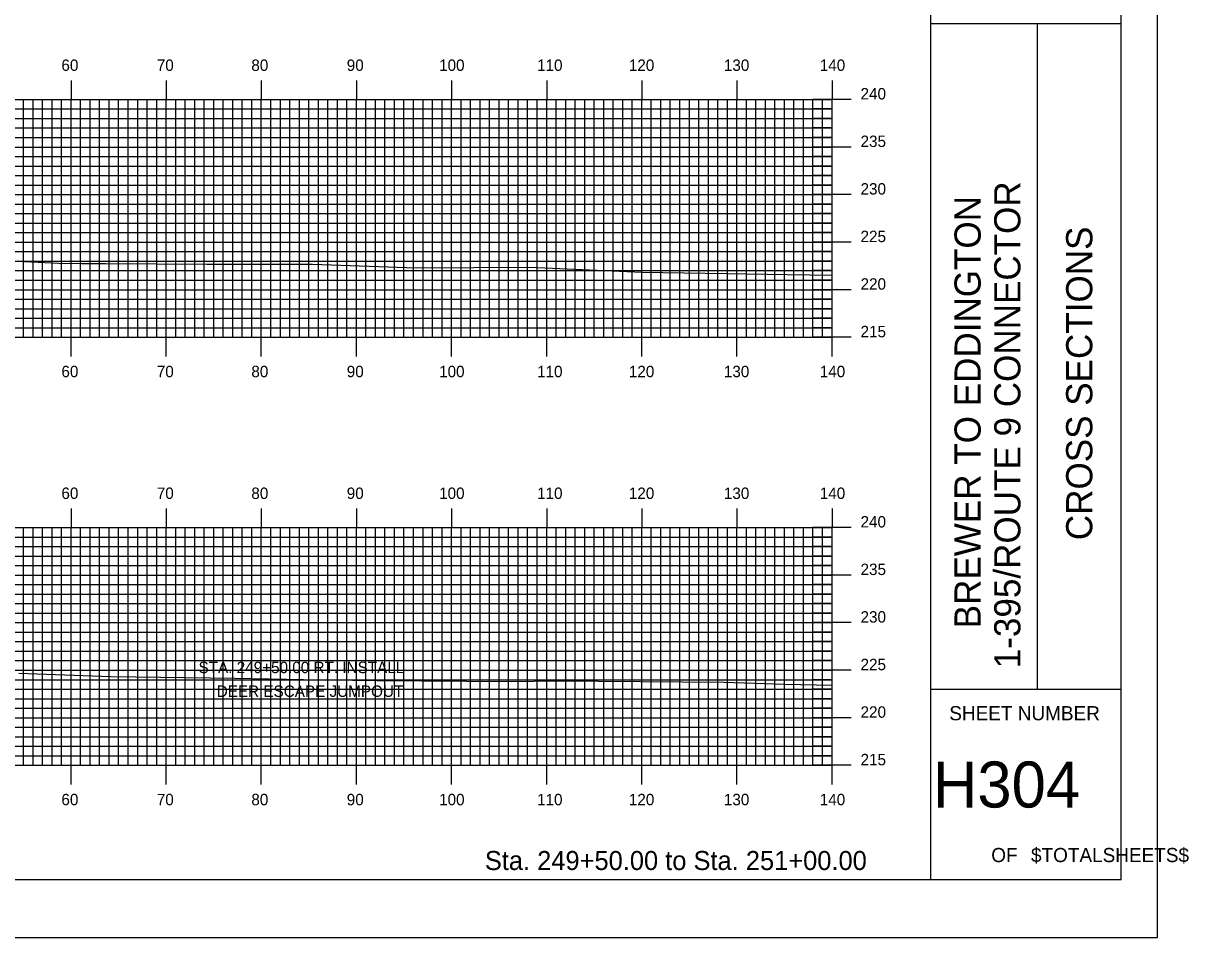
# Model space of a CAD drawing. Extents: x 1803897 to 1804240, y 442591 to 442811.
# Drawn here: x 1804117.6 to 1804240.2, y 442590.5 to 442686.7 of the extents above; entities that cross this region are included whole.
import ezdxf

# ---------------------------------------------------------------- set-up
doc = ezdxf.new("R2010")
doc.units = 0
for name, color, linetype in [('BORDER', 7, 'Continuous'), ('D_Text_Standard', 7, 'Continuous'), ('H_V ANNOTATION', 7, 'Continuous'), ('MAJOR', 7, 'Continuous'), ('MINOR', 7, 'Continuous'), ('PLOT BOUNDARY', 7, 'Continuous'), ('S_Roadway_Centerline', 7, 'Continuous')]:
    doc.layers.add(name, color=color, linetype=linetype)

msp = doc.modelspace()

# ---------------------------------------------------------------- linework, layer by layer
at = {"layer": 'BORDER'}
for p, q in [((1804213.05, 442596.67), (1804213.05, 442806.67)), ((1804213.05, 442686.67), (1804233.05, 442686.67)), ((1804224.24, 442616.67), (1804224.24, 442686.67)), ((1804213.05, 442616.67), (1804233.05, 442616.67))]:
    msp.add_line(p, q, dxfattribs=at)
msp.add_lwpolyline([(1803913.05, 442596.67), (1804233.05, 442596.67), (1804233.05, 442806.67), (1803913.05, 442806.67)], close=True, dxfattribs=at)
at = {"layer": 'MAJOR'}
for p, q in [((1804122.65, 442680.67), (1804122.65, 442678.67)), ((1804132.65, 442680.67), (1804132.65, 442678.67)), ((1804142.65, 442680.67), (1804142.65, 442678.67)), ((1804152.65, 442680.67), (1804152.65, 442678.67)), ((1804162.65, 442680.67), (1804162.65, 442678.67)), ((1804172.65, 442680.67), (1804172.65, 442678.67)), ((1804182.65, 442680.67), (1804182.65, 442678.67)), ((1804192.65, 442680.67), (1804192.65, 442678.67)), ((1804202.65, 442680.67), (1804202.65, 442678.67)), ((1803922.65, 442678.67), (1804202.65, 442678.67)), ((1803922.65, 442678.67), (1804202.65, 442678.67)), ((1804122.65, 442653.67), (1804122.65, 442678.67)), ((1804132.65, 442653.67), (1804132.65, 442678.67)), ((1804142.65, 442653.67), (1804142.65, 442678.67)), ((1804152.65, 442653.67), (1804152.65, 442678.67)), ((1804162.65, 442653.67), (1804162.65, 442678.67)), ((1804172.65, 442653.67), (1804172.65, 442678.67)), ((1804182.65, 442653.67), (1804182.65, 442678.67)), ((1804192.65, 442653.67), (1804192.65, 442678.67)), ((1804204.66, 442678.67), (1804200.65, 442678.67)), ((1804202.65, 442653.67), (1804202.65, 442678.67)), ((1804202.65, 442653.67), (1804202.65, 442678.67)), ((1803922.65, 442673.67), (1804202.65, 442673.67)), ((1804204.66, 442673.67), (1804200.65, 442673.67)), ((1803922.65, 442668.67), (1804202.65, 442668.67)), ((1804204.66, 442668.67), (1804200.65, 442668.67)), ((1803922.65, 442663.67), (1804202.65, 442663.67)), ((1804204.66, 442663.67), (1804200.65, 442663.67)), ((1803922.65, 442658.67), (1804202.65, 442658.67)), ((1804204.66, 442658.67), (1804200.65, 442658.67)), ((1803922.65, 442653.67), (1804202.65, 442653.67)), ((1803922.65, 442653.67), (1804202.65, 442653.67)), ((1804122.65, 442651.66), (1804122.65, 442653.67)), ((1804132.65, 442651.66), (1804132.65, 442653.67)), ((1804142.65, 442651.66), (1804142.65, 442653.67)), ((1804152.65, 442651.66), (1804152.65, 442653.67)), ((1804162.65, 442651.66), (1804162.65, 442653.67)), ((1804172.65, 442651.66), (1804172.65, 442653.67)), ((1804182.65, 442651.66), (1804182.65, 442653.67)), ((1804192.65, 442651.66), (1804192.65, 442653.67)), ((1804204.66, 442653.67), (1804200.65, 442653.67)), ((1804202.65, 442651.66), (1804202.65, 442653.67)), ((1804122.65, 442635.67), (1804122.65, 442633.67)), ((1804132.65, 442635.67), (1804132.65, 442633.67)), ((1804142.65, 442635.67), (1804142.65, 442633.67)), ((1804152.65, 442635.67), (1804152.65, 442633.67)), ((1804162.65, 442635.67), (1804162.65, 442633.67)), ((1804172.65, 442635.67), (1804172.65, 442633.67)), ((1804182.65, 442635.67), (1804182.65, 442633.67)), ((1804192.65, 442635.67), (1804192.65, 442633.67)), ((1804202.65, 442635.67), (1804202.65, 442633.67)), ((1803922.65, 442633.67), (1804202.65, 442633.67)), ((1803922.65, 442633.67), (1804202.65, 442633.67)), ((1804122.65, 442608.67), (1804122.65, 442633.67)), ((1804132.65, 442608.67), (1804132.65, 442633.67)), ((1804142.65, 442608.67), (1804142.65, 442633.67)), ((1804152.65, 442608.67), (1804152.65, 442633.67)), ((1804162.65, 442608.67), (1804162.65, 442633.67)), ((1804172.65, 442608.67), (1804172.65, 442633.67)), ((1804182.65, 442608.67), (1804182.65, 442633.67)), ((1804192.65, 442608.67), (1804192.65, 442633.67)), ((1804204.66, 442633.67), (1804200.65, 442633.67)), ((1804202.65, 442608.67), (1804202.65, 442633.67)), ((1804202.65, 442608.67), (1804202.65, 442633.67)), ((1803922.65, 442628.67), (1804202.65, 442628.67)), ((1804204.66, 442628.67), (1804200.65, 442628.67)), ((1803922.65, 442623.67), (1804202.65, 442623.67)), ((1804204.66, 442623.67), (1804200.65, 442623.67)), ((1803922.65, 442618.67), (1804202.65, 442618.67)), ((1804204.66, 442618.67), (1804200.65, 442618.67)), ((1803922.65, 442613.67), (1804202.65, 442613.67)), ((1804204.66, 442613.67), (1804200.65, 442613.67)), ((1803922.65, 442608.67), (1804202.65, 442608.67)), ((1803922.65, 442608.67), (1804202.65, 442608.67)), ((1804122.65, 442606.66), (1804122.65, 442608.67)), ((1804132.65, 442606.66), (1804132.65, 442608.67)), ((1804142.65, 442606.66), (1804142.65, 442608.67)), ((1804152.65, 442606.66), (1804152.65, 442608.67)), ((1804162.65, 442606.66), (1804162.65, 442608.67)), ((1804172.65, 442606.66), (1804172.65, 442608.67)), ((1804182.65, 442606.66), (1804182.65, 442608.67)), ((1804192.65, 442606.66), (1804192.65, 442608.67)), ((1804204.66, 442608.67), (1804200.65, 442608.67)), ((1804202.65, 442606.66), (1804202.65, 442608.67))]:
    msp.add_line(p, q, dxfattribs=at)
at = {"layer": 'MINOR'}
for p, q in [((1804117.65, 442653.67), (1804117.65, 442678.67)), ((1804118.65, 442653.67), (1804118.65, 442678.67)), ((1804119.65, 442653.67), (1804119.65, 442678.67)), ((1804120.65, 442653.67), (1804120.65, 442678.67)), ((1804121.65, 442653.67), (1804121.65, 442678.67)), ((1804123.65, 442653.67), (1804123.65, 442678.67)), ((1804124.65, 442653.67), (1804124.65, 442678.67)), ((1804125.65, 442653.67), (1804125.65, 442678.67)), ((1804126.65, 442653.67), (1804126.65, 442678.67)), ((1804127.65, 442653.67), (1804127.65, 442678.67)), ((1804128.65, 442653.67), (1804128.65, 442678.67)), ((1804129.65, 442653.67), (1804129.65, 442678.67)), ((1804130.65, 442653.67), (1804130.65, 442678.67)), ((1804131.65, 442653.67), (1804131.65, 442678.67)), ((1804133.65, 442653.67), (1804133.65, 442678.67)), ((1804134.65, 442653.67), (1804134.65, 442678.67)), ((1804135.65, 442653.67), (1804135.65, 442678.67)), ((1804136.65, 442653.67), (1804136.65, 442678.67)), ((1804137.65, 442653.67), (1804137.65, 442678.67)), ((1804138.65, 442653.67), (1804138.65, 442678.67)), ((1804139.65, 442653.67), (1804139.65, 442678.67)), ((1804140.65, 442653.67), (1804140.65, 442678.67)), ((1804141.65, 442653.67), (1804141.65, 442678.67)), ((1804143.65, 442653.67), (1804143.65, 442678.67)), ((1804144.65, 442653.67), (1804144.65, 442678.67)), ((1804145.65, 442653.67), (1804145.65, 442678.67)), ((1804146.65, 442653.67), (1804146.65, 442678.67)), ((1804147.65, 442653.67), (1804147.65, 442678.67)), ((1804148.65, 442653.67), (1804148.65, 442678.67)), ((1804149.65, 442653.67), (1804149.65, 442678.67)), ((1804150.65, 442653.67), (1804150.65, 442678.67)), ((1804151.65, 442653.67), (1804151.65, 442678.67)), ((1804153.65, 442653.67), (1804153.65, 442678.67)), ((1804154.65, 442653.67), (1804154.65, 442678.67)), ((1804155.65, 442653.67), (1804155.65, 442678.67)), ((1804156.65, 442653.67), (1804156.65, 442678.67)), ((1804157.65, 442653.67), (1804157.65, 442678.67)), ((1804158.65, 442653.67), (1804158.65, 442678.67)), ((1804159.65, 442653.67), (1804159.65, 442678.67)), ((1804160.65, 442653.67), (1804160.65, 442678.67)), ((1804161.65, 442653.67), (1804161.65, 442678.67)), ((1804163.65, 442653.67), (1804163.65, 442678.67)), ((1804164.65, 442653.67), (1804164.65, 442678.67)), ((1804165.65, 442653.67), (1804165.65, 442678.67)), ((1804166.65, 442653.67), (1804166.65, 442678.67)), ((1804167.65, 442653.67), (1804167.65, 442678.67)), ((1804168.65, 442653.67), (1804168.65, 442678.67)), ((1804169.65, 442653.67), (1804169.65, 442678.67)), ((1804170.65, 442653.67), (1804170.65, 442678.67)), ((1804171.65, 442653.67), (1804171.65, 442678.67)), ((1804173.65, 442653.67), (1804173.65, 442678.67)), ((1804174.65, 442653.67), (1804174.65, 442678.67)), ((1804175.65, 442653.67), (1804175.65, 442678.67)), ((1804176.65, 442653.67), (1804176.65, 442678.67)), ((1804177.65, 442653.67), (1804177.65, 442678.67)), ((1804178.65, 442653.67), (1804178.65, 442678.67)), ((1804179.65, 442653.67), (1804179.65, 442678.67)), ((1804180.65, 442653.67), (1804180.65, 442678.67)), ((1804181.65, 442653.67), (1804181.65, 442678.67)), ((1804183.65, 442653.67), (1804183.65, 442678.67)), ((1804184.65, 442653.67), (1804184.65, 442678.67)), ((1804185.65, 442653.67), (1804185.65, 442678.67)), ((1804186.65, 442653.67), (1804186.65, 442678.67)), ((1804187.65, 442653.67), (1804187.65, 442678.67)), ((1804188.65, 442653.67), (1804188.65, 442678.67)), ((1804189.65, 442653.67), (1804189.65, 442678.67)), ((1804190.65, 442653.67), (1804190.65, 442678.67)), ((1804191.65, 442653.67), (1804191.65, 442678.67)), ((1804193.65, 442653.67), (1804193.65, 442678.67)), ((1804194.65, 442653.67), (1804194.65, 442678.67)), ((1804195.65, 442653.67), (1804195.65, 442678.67)), ((1804196.65, 442653.67), (1804196.65, 442678.67)), ((1804197.65, 442653.67), (1804197.65, 442678.67)), ((1804198.65, 442653.67), (1804198.65, 442678.67)), ((1804199.65, 442653.67), (1804199.65, 442678.67)), ((1804200.65, 442653.67), (1804200.65, 442678.67)), ((1804201.65, 442653.67), (1804201.65, 442678.67)), ((1803922.65, 442677.67), (1804202.65, 442677.67)), ((1804202.65, 442677.67), (1804200.65, 442677.67)), ((1803922.65, 442676.67), (1804202.65, 442676.67)), ((1803922.65, 442675.67), (1804202.65, 442675.67)), ((1804202.65, 442676.67), (1804200.65, 442676.67)), ((1804202.65, 442675.67), (1804200.65, 442675.67)), ((1803922.65, 442674.67), (1804202.65, 442674.67)), ((1804202.65, 442674.67), (1804200.65, 442674.67)), ((1803922.65, 442672.67), (1804202.65, 442672.67)), ((1804202.65, 442672.67), (1804200.65, 442672.67)), ((1803922.65, 442671.67), (1804202.65, 442671.67)), ((1803922.65, 442670.67), (1804202.65, 442670.67)), ((1804202.65, 442671.67), (1804200.65, 442671.67)), ((1804202.65, 442670.67), (1804200.65, 442670.67)), ((1803922.65, 442669.67), (1804202.65, 442669.67)), ((1804202.65, 442669.67), (1804200.65, 442669.67)), ((1803922.65, 442667.67), (1804202.65, 442667.67)), ((1804202.65, 442667.67), (1804200.65, 442667.67)), ((1803922.65, 442666.67), (1804202.65, 442666.67)), ((1804202.65, 442666.67), (1804200.65, 442666.67)), ((1803922.65, 442665.67), (1804202.65, 442665.67)), ((1803922.65, 442664.67), (1804202.65, 442664.67)), ((1804202.65, 442665.67), (1804200.65, 442665.67)), ((1804202.65, 442664.67), (1804200.65, 442664.67)), ((1803922.65, 442662.67), (1804202.65, 442662.67)), ((1804202.65, 442662.67), (1804200.65, 442662.67)), ((1803922.65, 442661.67), (1804202.65, 442661.67)), ((1804202.65, 442661.67), (1804200.65, 442661.67)), ((1803922.65, 442660.67), (1804202.65, 442660.67)), ((1803922.65, 442659.67), (1804202.65, 442659.67)), ((1804202.65, 442660.67), (1804200.65, 442660.67)), ((1804202.65, 442659.67), (1804200.65, 442659.67)), ((1803922.65, 442657.67), (1804202.65, 442657.67)), ((1804202.65, 442657.67), (1804200.65, 442657.67)), ((1803922.65, 442656.67), (1804202.65, 442656.67)), ((1804202.65, 442656.67), (1804200.65, 442656.67)), ((1803922.65, 442655.67), (1804202.65, 442655.67)), ((1804202.65, 442655.67), (1804200.65, 442655.67)), ((1803922.65, 442654.67), (1804202.65, 442654.67)), ((1804202.65, 442654.67), (1804200.65, 442654.67)), ((1804117.65, 442608.67), (1804117.65, 442633.67)), ((1804118.65, 442608.67), (1804118.65, 442633.67)), ((1804119.65, 442608.67), (1804119.65, 442633.67)), ((1804120.65, 442608.67), (1804120.65, 442633.67)), ((1804121.65, 442608.67), (1804121.65, 442633.67)), ((1804123.65, 442608.67), (1804123.65, 442633.67)), ((1804124.65, 442608.67), (1804124.65, 442633.67)), ((1804125.65, 442608.67), (1804125.65, 442633.67)), ((1804126.65, 442608.67), (1804126.65, 442633.67)), ((1804127.65, 442608.67), (1804127.65, 442633.67)), ((1804128.65, 442608.67), (1804128.65, 442633.67)), ((1804129.65, 442608.67), (1804129.65, 442633.67)), ((1804130.65, 442608.67), (1804130.65, 442633.67)), ((1804131.65, 442608.67), (1804131.65, 442633.67)), ((1804133.65, 442608.67), (1804133.65, 442633.67)), ((1804134.65, 442608.67), (1804134.65, 442633.67)), ((1804135.65, 442608.67), (1804135.65, 442633.67)), ((1804136.65, 442608.67), (1804136.65, 442633.67)), ((1804137.65, 442608.67), (1804137.65, 442633.67)), ((1804138.65, 442608.67), (1804138.65, 442633.67)), ((1804139.65, 442608.67), (1804139.65, 442633.67)), ((1804140.65, 442608.67), (1804140.65, 442633.67)), ((1804141.65, 442608.67), (1804141.65, 442633.67)), ((1804143.65, 442608.67), (1804143.65, 442633.67)), ((1804144.65, 442608.67), (1804144.65, 442633.67)), ((1804145.65, 442608.67), (1804145.65, 442633.67)), ((1804146.65, 442608.67), (1804146.65, 442633.67)), ((1804147.65, 442608.67), (1804147.65, 442633.67)), ((1804148.65, 442608.67), (1804148.65, 442633.67)), ((1804149.65, 442608.67), (1804149.65, 442633.67)), ((1804150.65, 442608.67), (1804150.65, 442633.67)), ((1804151.65, 442608.67), (1804151.65, 442633.67)), ((1804153.65, 442608.67), (1804153.65, 442633.67)), ((1804154.65, 442608.67), (1804154.65, 442633.67)), ((1804155.65, 442608.67), (1804155.65, 442633.67)), ((1804156.65, 442608.67), (1804156.65, 442633.67)), ((1804157.65, 442608.67), (1804157.65, 442633.67)), ((1804158.65, 442608.67), (1804158.65, 442633.67)), ((1804159.65, 442608.67), (1804159.65, 442633.67)), ((1804160.65, 442608.67), (1804160.65, 442633.67)), ((1804161.65, 442608.67), (1804161.65, 442633.67)), ((1804163.65, 442608.67), (1804163.65, 442633.67)), ((1804164.65, 442608.67), (1804164.65, 442633.67)), ((1804165.65, 442608.67), (1804165.65, 442633.67)), ((1804166.65, 442608.67), (1804166.65, 442633.67)), ((1804167.65, 442608.67), (1804167.65, 442633.67)), ((1804168.65, 442608.67), (1804168.65, 442633.67)), ((1804169.65, 442608.67), (1804169.65, 442633.67)), ((1804170.65, 442608.67), (1804170.65, 442633.67)), ((1804171.65, 442608.67), (1804171.65, 442633.67)), ((1804173.65, 442608.67), (1804173.65, 442633.67)), ((1804174.65, 442608.67), (1804174.65, 442633.67)), ((1804175.65, 442608.67), (1804175.65, 442633.67)), ((1804176.65, 442608.67), (1804176.65, 442633.67)), ((1804177.65, 442608.67), (1804177.65, 442633.67)), ((1804178.65, 442608.67), (1804178.65, 442633.67)), ((1804179.65, 442608.67), (1804179.65, 442633.67)), ((1804180.65, 442608.67), (1804180.65, 442633.67)), ((1804181.65, 442608.67), (1804181.65, 442633.67)), ((1804183.65, 442608.67), (1804183.65, 442633.67)), ((1804184.65, 442608.67), (1804184.65, 442633.67)), ((1804185.65, 442608.67), (1804185.65, 442633.67)), ((1804186.65, 442608.67), (1804186.65, 442633.67)), ((1804187.65, 442608.67), (1804187.65, 442633.67)), ((1804188.65, 442608.67), (1804188.65, 442633.67)), ((1804189.65, 442608.67), (1804189.65, 442633.67)), ((1804190.65, 442608.67), (1804190.65, 442633.67)), ((1804191.65, 442608.67), (1804191.65, 442633.67)), ((1804193.65, 442608.67), (1804193.65, 442633.67)), ((1804194.65, 442608.67), (1804194.65, 442633.67)), ((1804195.65, 442608.67), (1804195.65, 442633.67)), ((1804196.65, 442608.67), (1804196.65, 442633.67)), ((1804197.65, 442608.67), (1804197.65, 442633.67)), ((1804198.65, 442608.67), (1804198.65, 442633.67)), ((1804199.65, 442608.67), (1804199.65, 442633.67)), ((1804200.65, 442608.67), (1804200.65, 442633.67)), ((1804201.65, 442608.67), (1804201.65, 442633.67)), ((1803922.65, 442632.67), (1804202.65, 442632.67)), ((1803922.65, 442631.67), (1804202.65, 442631.67)), ((1804202.65, 442632.67), (1804200.65, 442632.67)), ((1804202.65, 442631.67), (1804200.65, 442631.67)), ((1803922.65, 442630.67), (1804202.65, 442630.67)), ((1804202.65, 442630.67), (1804200.65, 442630.67)), ((1803922.65, 442629.67), (1804202.65, 442629.67)), ((1804202.65, 442629.67), (1804200.65, 442629.67)), ((1803922.65, 442627.67), (1804202.65, 442627.67)), ((1803922.65, 442626.67), (1804202.65, 442626.67)), ((1804202.65, 442627.67), (1804200.65, 442627.67)), ((1804202.65, 442626.67), (1804200.65, 442626.67)), ((1803922.65, 442625.67), (1804202.65, 442625.67)), ((1804202.65, 442625.67), (1804200.65, 442625.67)), ((1803922.65, 442624.67), (1804202.65, 442624.67)), ((1804202.65, 442624.67), (1804200.65, 442624.67)), ((1803922.65, 442622.67), (1804202.65, 442622.67)), ((1803922.65, 442621.67), (1804202.65, 442621.67)), ((1804202.65, 442622.67), (1804200.65, 442622.67)), ((1804202.65, 442621.67), (1804200.65, 442621.67)), ((1803922.65, 442620.67), (1804202.65, 442620.67)), ((1804202.65, 442620.67), (1804200.65, 442620.67)), ((1803922.65, 442619.67), (1804202.65, 442619.67)), ((1804202.65, 442619.67), (1804200.65, 442619.67)), ((1803922.65, 442617.67), (1804202.65, 442617.67)), ((1804202.65, 442617.67), (1804200.65, 442617.67)), ((1803922.65, 442616.67), (1804202.65, 442616.67)), ((1803922.65, 442615.67), (1804202.65, 442615.67)), ((1804202.65, 442616.67), (1804200.65, 442616.67)), ((1804202.65, 442615.67), (1804200.65, 442615.67)), ((1803922.65, 442614.67), (1804202.65, 442614.67)), ((1804202.65, 442614.67), (1804200.65, 442614.67)), ((1803922.65, 442612.67), (1804202.65, 442612.67)), ((1804202.65, 442612.67), (1804200.65, 442612.67)), ((1803922.65, 442611.67), (1804202.65, 442611.67)), ((1803922.65, 442610.67), (1804202.65, 442610.67)), ((1804202.65, 442611.67), (1804200.65, 442611.67)), ((1804202.65, 442610.67), (1804200.65, 442610.67)), ((1803922.65, 442609.67), (1804202.65, 442609.67)), ((1804202.65, 442609.67), (1804200.65, 442609.67))]:
    msp.add_line(p, q, dxfattribs=at)
at = {"layer": 'PLOT BOUNDARY'}
msp.add_lwpolyline([(1803896.87, 442590.55), (1804236.87, 442590.55), (1804236.87, 442810.55), (1803896.87, 442810.55)], close=True, dxfattribs=at)
at = {"layer": 'S_Roadway_Centerline'}
for points in [[(1804112.68, 442661.87), (1804121.32, 442661.47), (1804123.77, 442661.41), (1804126.25, 442661.41), (1804136.92, 442661.34), (1804147.06, 442661.35), (1804148.02, 442661.34), (1804158.94, 442660.96), (1804171.07, 442661.03), (1804171.68, 442661.02), (1804182.64, 442660.51), (1804191.57, 442660.38), (1804197.98, 442660.28), (1804202.65, 442660.18)], [(1804117.17, 442618.34), (1804126.83, 442618), (1804139.91, 442617.82), (1804147.09, 442617.7), (1804154.8, 442617.59), (1804168.94, 442617.48), (1804173.68, 442617.55), (1804191.3, 442617.4), (1804197.7, 442617.21), (1804202.65, 442617.08)]]:
    msp.add_lwpolyline(points, dxfattribs=at)

# ---------------------------------------------------------------- texts
at = {"layer": 'BORDER'}
for s, p in [('1-395/ROUTE 9 CONNECTOR', (1804222.46, 442618.87)), ('BREWER TO EDDINGTON', (1804218.28, 442623.07)), ('CROSS SECTIONS', (1804230.02, 442632.34))]:
    msp.add_text(s, height=2.7557, rotation=90, dxfattribs=at).set_placement(p)
for s, height, p in [('SHEET NUMBER', 1.4905, (1804214.98, 442613.4)), ('H304', 4.839, (1804213.26, 442604.23)), ('OF', 1.491, (1804219.39, 442598.49)), ('$TOTALSHEETS$', 1.4905, (1804223.57, 442598.49))]:
    msp.add_text(s, height=height, dxfattribs=at).set_placement(p)
at = {"layer": 'D_Text_Standard'}
for s, p in [('STA. 249+50.00 RT. INSTALL ', (1804136.05, 442618.36)), ('DEER ESCAPE JUMPOUT', (1804137.96, 442615.86))]:
    msp.add_text(s, height=1.2, dxfattribs=at).set_placement(p)
at = {"layer": 'H_V ANNOTATION'}
for s, height, p in [('60', 1.2, (1804121.63, 442681.67)), ('70', 1.2, (1804131.66, 442681.67)), ('80', 1.2, (1804141.6, 442681.67)), ('90', 1.2, (1804151.63, 442681.67)), ('100', 1.2, (1804161.34, 442681.67)), ('110', 1.2, (1804171.64, 442681.67)), ('120', 1.2, (1804181.29, 442681.67)), ('130', 1.2, (1804191.28, 442681.67)), ('140', 1.2, (1804201.36, 442681.67)), ('240', 1.2, (1804205.65, 442678.67)), ('235', 1.2, (1804205.65, 442673.67)), ('230', 1.2, (1804205.65, 442668.67)), ('225', 1.2, (1804205.65, 442663.67)), ('220', 1.2, (1804205.65, 442658.67)), ('215', 1.2, (1804205.65, 442653.67)), ('60', 1.2, (1804121.63, 442649.47)), ('70', 1.2, (1804131.66, 442649.47)), ('80', 1.2, (1804141.6, 442649.47)), ('90', 1.2, (1804151.63, 442649.47)), ('100', 1.2, (1804161.34, 442649.47)), ('110', 1.2, (1804171.64, 442649.47)), ('120', 1.2, (1804181.29, 442649.47)), ('130', 1.2, (1804191.28, 442649.47)), ('140', 1.2, (1804201.36, 442649.47)), ('60', 1.2, (1804121.63, 442636.67)), ('70', 1.2, (1804131.66, 442636.67)), ('80', 1.2, (1804141.6, 442636.67)), ('90', 1.2, (1804151.63, 442636.67)), ('100', 1.2, (1804161.34, 442636.67)), ('110', 1.2, (1804171.64, 442636.67)), ('120', 1.2, (1804181.29, 442636.67)), ('130', 1.2, (1804191.28, 442636.67)), ('140', 1.2, (1804201.36, 442636.67)), ('240', 1.2, (1804205.65, 442633.67)), ('235', 1.2, (1804205.65, 442628.67)), ('230', 1.2, (1804205.65, 442623.67)), ('225', 1.2, (1804205.65, 442618.67)), ('220', 1.2, (1804205.65, 442613.67)), ('215', 1.2, (1804205.65, 442608.67)), ('60', 1.2, (1804121.63, 442604.47)), ('70', 1.2, (1804131.66, 442604.47)), ('80', 1.2, (1804141.6, 442604.47)), ('90', 1.2, (1804151.63, 442604.47)), ('100', 1.2, (1804161.34, 442604.47)), ('110', 1.2, (1804171.64, 442604.47)), ('120', 1.2, (1804181.29, 442604.47)), ('130', 1.2, (1804191.28, 442604.47)), ('140', 1.2, (1804201.36, 442604.47)), ('Sta. 249+50.00 to Sta. 251+00.00', 2.0004, (1804166.15, 442597.66))]:
    msp.add_text(s, height=height, dxfattribs=at).set_placement(p)

doc.saveas('drawing.dxf')
